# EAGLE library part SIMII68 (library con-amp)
AMP connector
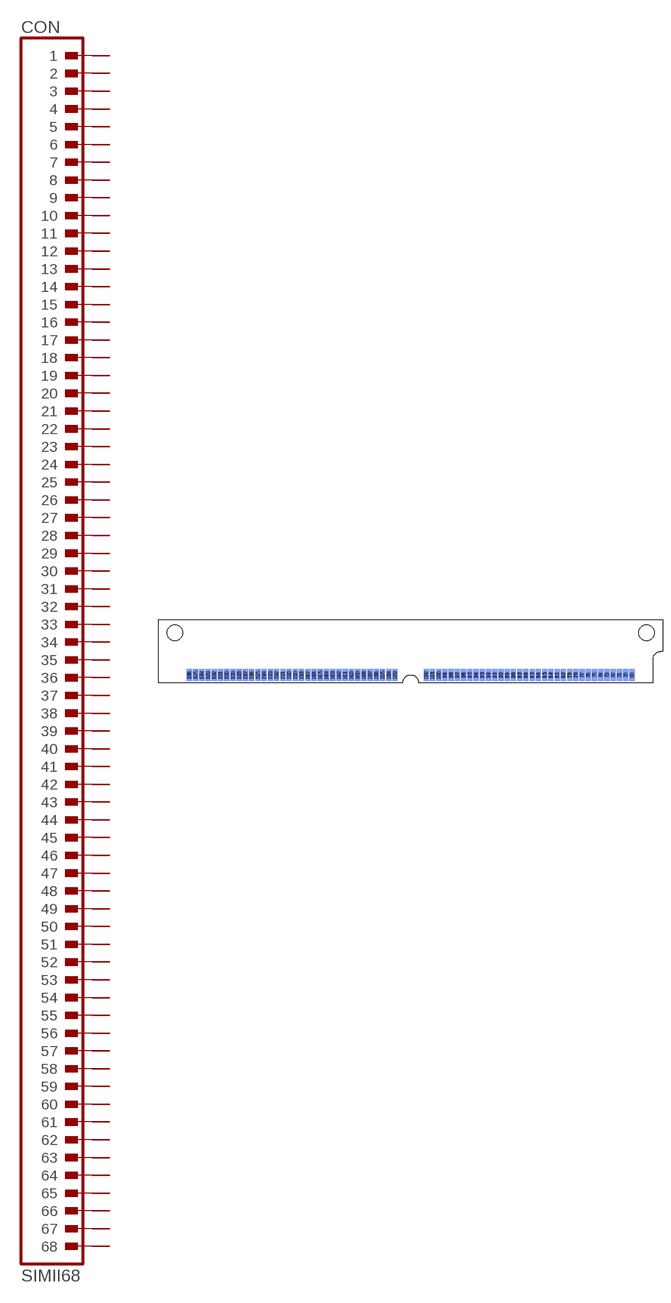
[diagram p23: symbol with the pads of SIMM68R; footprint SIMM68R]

Designator prefix CON

## SIMII68 (OC_FARNELL: unknown; OC_NEWARK: unknown)  [SIMM68R]
1  1  pas
2  2  pas
3  3  pas
4  4  pas
5  5  pas
6  6  pas
7  7  pas
8  8  pas
9  9  pas
10  10  pas
11  11  pas
12  12  pas
13  13  pas
14  14  pas
15  15  pas
16  16  pas
17  17  pas
18  18  pas
19  19  pas
20  20  pas
21  21  pas
22  22  pas
23  23  pas
24  24  pas
25  25  pas
26  26  pas
27  27  pas
28  28  pas
29  29  pas
30  30  pas
31  31  pas
32  32  pas
33  33  pas
34  34  pas
35  35  pas
36  36  pas
37  37  pas
38  38  pas
39  39  pas
40  40  pas
41  41  pas
42  42  pas
43  43  pas
44  44  pas
45  45  pas
46  46  pas
47  47  pas
48  48  pas
49  49  pas
50  50  pas
51  51  pas
52  52  pas
53  53  pas
54  54  pas
55  55  pas
56  56  pas
57  57  pas
58  58  pas
59  59  pas
60  60  pas
61  61  pas
62  62  pas
63  63  pas
64  64  pas
65  65  pas
66  66  pas
67  67  pas
68  68  pas
69  69  pas
70  70  pas
71  71  pas
72  72  pas
73  73  pas
74  74  pas
75  75  pas
76  76  pas
77  77  pas
78  78  pas
79  79  pas
80  80  pas
81  81  pas
82  82  pas
83  83  pas
84  84  pas
85  85  pas
86  86  pas
87  87  pas
88  88  pas
89  89  pas
90  90  pas
91  91  pas
92  92  pas
93  93  pas
94  94  pas
95  95  pas
96  96  pas
97  97  pas
98  98  pas
99  99  pas
100  100  pas
101  101  pas
102  102  pas
103  103  pas
104  104  pas
105  105  pas
106  106  pas
107  107  pas
108  108  pas
109  109  pas
110  110  pas
111  111  pas
112  112  pas
113  113  pas
114  114  pas
115  115  pas
116  116  pas
117  117  pas
118  118  pas
119  119  pas
120  120  pas
121  121  pas
122  122  pas
123  123  pas
124  124  pas
125  125  pas
126  126  pas
127  127  pas
128  128  pas
129  129  pas
130  130  pas
131  131  pas
132  132  pas
133  133  pas
134  134  pas
135  135  pas
136  136  pas

## Footprint SIMM68R (pad centres in mm)
SIMM II 68 Right Polarization
smd 1.041 x 2.54: 1 45.085,-8.636; 2 43.815,-8.636; 3 42.545,-8.636; 4 41.275,-8.636; 5 40.005,-8.636; 6 38.735,-8.636; 7 37.465,-8.636; 8 36.195,-8.636; 9 34.925,-8.636; 10 33.655,-8.636; 11 32.385,-8.636; 12 31.115,-8.636; 13 29.845,-8.636; 14 28.575,-8.636; 15 27.305,-8.636; 16 26.035,-8.636; 17 24.765,-8.636; 18 23.495,-8.636; 19 22.225,-8.636; 20 20.955,-8.636; 21 19.685,-8.636; 22 18.415,-8.636; 23 17.145,-8.636; 24 15.875,-8.636; 25 14.605,-8.636; 26 13.335,-8.636; 27 12.065,-8.636; 28 10.795,-8.636; 29 9.525,-8.636; 30 8.255,-8.636; 31 6.985,-8.636; 32 5.715,-8.636; 33 4.445,-8.636; 34 3.175,-8.636; 35 -3.175,-8.636; 36 -4.445,-8.636; 37 -5.715,-8.636; 38 -6.985,-8.636; 39 -8.255,-8.636; 40 -9.525,-8.636; 41 -10.795,-8.636; 42 -12.065,-8.636; 43 -13.335,-8.636; 44 -14.605,-8.636; 45 -15.875,-8.636; 46 -17.145,-8.636; 47 -18.415,-8.636; 48 -19.685,-8.636; 49 -20.955,-8.636; 50 -22.225,-8.636; 51 -23.495,-8.636; 52 -24.765,-8.636; 53 -26.035,-8.636; 54 -27.305,-8.636; 55 -28.575,-8.636; 56 -29.845,-8.636; 57 -31.115,-8.636; 58 -32.385,-8.636; 59 -33.655,-8.636; 60 -34.925,-8.636; 61 -36.195,-8.636; 62 -37.465,-8.636; 63 -38.735,-8.636; 64 -40.005,-8.636; 65 -41.275,-8.636; 66 -42.545,-8.636; 67 -43.815,-8.636; 68 -45.085,-8.636
smd 1.041 x 2.54 bottom: 69 45.085,-8.636; 70 43.815,-8.636; 71 42.545,-8.636; 72 41.275,-8.636; 73 40.005,-8.636; 74 38.735,-8.636; 75 37.465,-8.636; 76 36.195,-8.636; 77 34.925,-8.636; 78 33.655,-8.636; 79 32.385,-8.636; 80 31.115,-8.636; 81 29.845,-8.636; 82 28.575,-8.636; 83 27.305,-8.636; 84 26.035,-8.636; 85 24.765,-8.636; 86 23.495,-8.636; 87 22.225,-8.636; 88 20.955,-8.636; 89 19.685,-8.636; 90 18.415,-8.636; 91 17.145,-8.636; 92 15.875,-8.636; 93 14.605,-8.636; 94 13.335,-8.636; 95 12.065,-8.636; 96 10.795,-8.636; 97 9.525,-8.636; 98 8.255,-8.636; 99 6.985,-8.636; 100 5.715,-8.636; 101 4.445,-8.636; 102 3.175,-8.636; 103 -3.175,-8.636; 104 -4.445,-8.636; 105 -5.715,-8.636; 106 -6.985,-8.636; 107 -8.255,-8.636; 108 -9.525,-8.636; 109 -10.795,-8.636; 110 -12.065,-8.636; 111 -13.335,-8.636; 112 -14.605,-8.636; 113 -15.875,-8.636; 114 -17.145,-8.636; 115 -18.415,-8.636; 116 -19.685,-8.636; 117 -20.955,-8.636; 118 -22.225,-8.636; 119 -23.495,-8.636; 120 -24.765,-8.636; 121 -26.035,-8.636; 122 -27.305,-8.636; 123 -28.575,-8.636; 124 -29.845,-8.636; 125 -31.115,-8.636; 126 -32.385,-8.636; 127 -33.655,-8.636; 128 -34.925,-8.636; 129 -36.195,-8.636; 130 -37.465,-8.636; 131 -38.735,-8.636; 132 -40.005,-8.636; 133 -41.275,-8.636; 134 -42.545,-8.636; 135 -43.815,-8.636; 136 -45.085,-8.636
hole 3.175 at -48.057,0
hole 3.175 at 48.057,0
